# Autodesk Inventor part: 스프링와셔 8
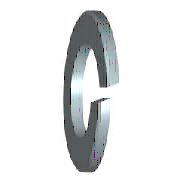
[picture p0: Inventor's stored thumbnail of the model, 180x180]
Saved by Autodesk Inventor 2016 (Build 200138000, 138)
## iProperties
Created: 2012-02
Part Number: 스프링와셔 8
Material: 강철, 연강
Description: 스프링 잠금 와셔
Document SubType Name: Modeling
Standard: KS B 1324
Designer: mduedu
Standards Organization: KS
Language: ko-KR
Size Designation: 번호 3 - 8
Categories: <MemberInstance><Categories><Category DisplayName="조임쇠" InternalName="e4da775c-781d-43d5-af7c-5136215cf5a6" Mnemonic="FSTN"><Category DisplayName="와셔" InternalN
Density: 1 g/cm^3
Appearance: 파란색 - 벽 페인트 - 광택
IsCustomPart: 1
Author: mduedu
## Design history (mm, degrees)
sketch "스케치1"
  geometry: C1 r 7.4 at (0, 0); C2 r 4.1 at (0, 0); 1 further point
  constraints: 2 centre point, 2 coincident
  dimensions: "d0" = 8.2 diameter of C2 (= SD1); "d1" = 14.8 diameter of C1 (= SD2)
extrude "본체" new body sketch "스케치1" distance "d2" = 2.5 (= SD); taper "d3" = 0 deg
sketch "스케치2"
  geometry: L1 (0, -4.1)-(0, 4.1) reference; L2 (2.5, 7.4)-(2.5, -7.4) reference; L3 (-1.2, 0)-(7.2, 0) reference; L4 (0, -0.5)-(2.5, 0.41); L5 (0, 0.5)-(2.5, 1.41)
  constraints: 4 end point, 4 point on line, 1 parallel
  dimensions: "d4" = 0.5 distance from line of L3 L4.start (= 0.2 x SD); "d5" = 0.5 distance from line of L3 L5.start (= 0.2 x SD); "d6" = 70 deg angle of L2 L4 (= FAWI)
extrude "절단부" cut sketch "스케치2" stored distance "d7" = 2.5 (= SD); taper "d8" = 0 deg
workaxis "Work Axis1"
workplane "Work Plane1"
body "Solid1"
other parameters: "SD1" = 8.2 [user parameter; used in 1 equation term], "SD2" = 14.8 [user parameter; used in 1 equation term], "SD" = 2.5 [user parameter; used in 4 equation terms], "FAWI" = 70 deg [user parameter; used in 1 equation term], "d9" = 0, "d10" = 0, "d11" = 0, "d12" = 0, "SDI" = 3.3 [user parameter], "NND" = 8 [user parameter]
